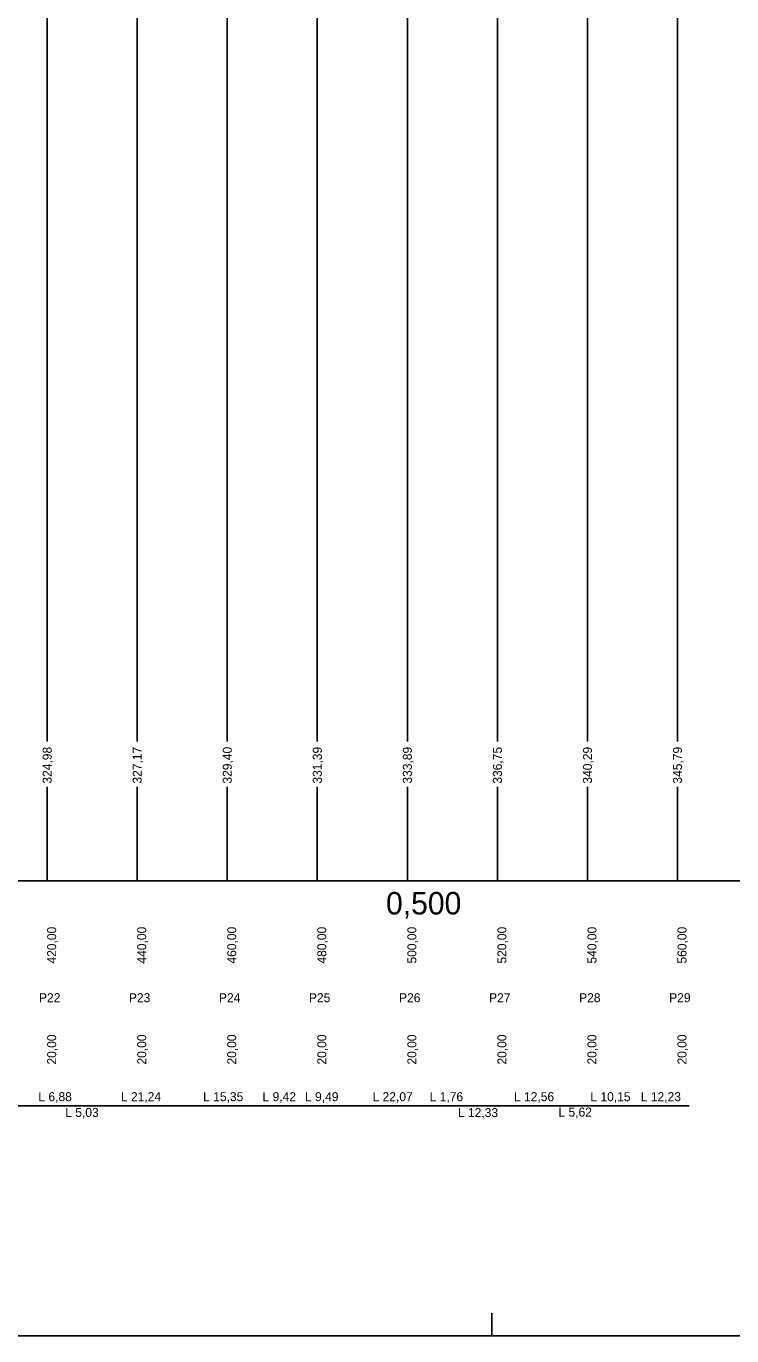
# Model space of a CAD drawing. Extents: x -500244 to -499404, y -1136557 to -1135632.
# Drawn here: x -499717.1 to -499560.4, y -1136556.6 to -1136265.5 of the extents above; entities that cross this region are included whole.
import ezdxf

# ---------------------------------------------------------------- set-up
doc = ezdxf.new("R2010")
doc.units = 0
for name, color, linetype in [('11', 7, 'Continuous'), ('13', 7, 'Continuous'), ('56', 7, 'Continuous'), ('hraniceABH', 7, 'Continuous')]:
    doc.layers.add(name, color=color, linetype=linetype)

msp = doc.modelspace()

# ---------------------------------------------------------------- linework, layer by layer
for points in [[(-499572.45, -1135747.48), (-499572.45, -1136385.42), (-499572.45, -1136395.42), (-499572.45, -1136424.49)], [(-499592.45, -1135802.47), (-499592.45, -1136385.42), (-499592.45, -1136395.42), (-499592.45, -1136424.49)], [(-499612.45, -1135837.95), (-499612.45, -1136385.42), (-499612.45, -1136395.42), (-499612.45, -1136424.49)], [(-499632.45, -1135866.56), (-499632.45, -1136385.42), (-499632.45, -1136395.42), (-499632.45, -1136424.49)], [(-499652.45, -1135891.55), (-499652.45, -1136385.42), (-499652.45, -1136395.42), (-499652.45, -1136424.49)], [(-499672.45, -1135911.4), (-499672.45, -1136385.42), (-499672.45, -1136395.42), (-499672.45, -1136424.49)], [(-499692.45, -1135933.71), (-499692.45, -1136385.42), (-499692.45, -1136395.42), (-499692.45, -1136424.49)], [(-499712.45, -1135955.6), (-499712.45, -1136385.42), (-499712.45, -1136395.42), (-499712.45, -1136424.49)], [(-499712.45, -1136434.55), (-499712.45, -1136455.42)], [(-499692.45, -1136434.55), (-499692.45, -1136455.42)], [(-499672.45, -1136434.55), (-499672.45, -1136455.42)], [(-499652.45, -1136434.55), (-499652.45, -1136455.42)], [(-499632.45, -1136434.55), (-499632.45, -1136455.42)], [(-499612.45, -1136434.55), (-499612.45, -1136455.42)], [(-499592.45, -1136434.55), (-499592.45, -1136455.42)], [(-499572.45, -1136434.55), (-499572.45, -1136455.42)], [(-499734.44, -1136505.42), (-499714.02, -1136505.42), (-499714.02, -1136505.42), (-499707.14, -1136505.42), (-499707.14, -1136505.42), (-499702.11, -1136505.42), (-499702.11, -1136505.42), (-499680.87, -1136505.42), (-499680.87, -1136505.42), (-499665.52, -1136505.42), (-499665.52, -1136505.42), (-499656.1, -1136505.42), (-499656.1, -1136505.42), (-499646.62, -1136505.42), (-499646.62, -1136505.42), (-499624.55, -1136505.42), (-499624.55, -1136505.42), (-499622.79, -1136505.42), (-499622.79, -1136505.42), (-499610.45, -1136505.42), (-499610.45, -1136505.42), (-499597.89, -1136505.42), (-499597.89, -1136505.42), (-499592.27, -1136505.42), (-499592.27, -1136505.42), (-499582.12, -1136505.42), (-499582.12, -1136505.42), (-499569.89, -1136505.42)]]:
    msp.add_lwpolyline(points)
at = {"layer": '56'}
for p, q in [((-499632.45, -1136455.42), (-499632.45, -1136454.42)), ((-500132.45, -1136455.42), (-499532.45, -1136455.42))]:
    msp.add_line(p, q, dxfattribs=at)
at = {"layer": 'hraniceABH'}
for p, q in [((-499613.68, -1136556.57), (-499613.68, -1136551.57)), ((-500243.68, -1136556.57), (-499403.68, -1136556.57))]:
    msp.add_line(p, q, dxfattribs=at)

# ---------------------------------------------------------------- texts
at = {"layer": '11'}
for s, p in [('324,98', (-499711.45, -1136433.84)), ('327,17', (-499691.45, -1136433.84)), ('329,40', (-499671.45, -1136433.83)), ('331,39', (-499651.45, -1136433.84)), ('333,89', (-499631.45, -1136433.84)), ('336,75', (-499611.45, -1136433.85)), ('340,29', (-499591.45, -1136433.84)), ('345,79', (-499571.45, -1136433.84)), ('420,00', (-499710.45, -1136473.83)), ('440,00', (-499690.45, -1136473.83)), ('460,00', (-499670.45, -1136473.83)), ('480,00', (-499650.45, -1136473.83)), ('500,00', (-499630.45, -1136473.83)), ('520,00', (-499610.45, -1136473.83)), ('540,00', (-499590.45, -1136473.83)), ('560,00', (-499570.45, -1136473.83)), ('20,00', (-499710.45, -1136496.28)), ('20,00', (-499690.45, -1136496.28)), ('20,00', (-499670.45, -1136496.28)), ('20,00', (-499650.45, -1136496.28)), ('20,00', (-499630.45, -1136496.28)), ('20,00', (-499610.45, -1136496.28)), ('20,00', (-499590.45, -1136496.28)), ('20,00', (-499570.45, -1136496.28))]:
    msp.add_text(s, height=2, rotation=90, dxfattribs=at).set_placement(p)
for s, p in [('P22', (-499714.27, -1136482.42)), ('P23', (-499694.3, -1136482.42)), ('P24', (-499674.29, -1136482.42)), ('P25', (-499654.31, -1136482.42)), ('P26', (-499634.3, -1136482.42)), ('P27', (-499614.3, -1136482.42)), ('P28', (-499594.3, -1136482.42)), ('P29', (-499574.3, -1136482.42)), ('L 6,88', (-499714.4, -1136504.42)), ('L 21,24', (-499696.08, -1136504.42)), ('L 15,35', (-499677.8, -1136504.42)), ('L 9,42', (-499664.62, -1136504.42)), ('L 9,49', (-499655.18, -1136504.42)), ('L 22,07', (-499640.18, -1136504.42)), ('L 1,76', (-499627.49, -1136504.42)), ('L 12,56', (-499608.77, -1136504.42)), ('L 10,15', (-499591.8, -1136504.42)), ('L 12,23', (-499580.6, -1136504.42)), ('L 5,03', (-499708.44, -1136507.92)), ('L 12,33', (-499621.22, -1136507.96)), ('L 5,62', (-499598.89, -1136507.85))]:
    msp.add_text(s, height=2, dxfattribs=at).set_placement(p)
at = {"layer": '13'}
msp.add_text('0,500', height=5, dxfattribs=at).set_placement((-499637.19, -1136462.92))

doc.saveas('drawing.dxf')
